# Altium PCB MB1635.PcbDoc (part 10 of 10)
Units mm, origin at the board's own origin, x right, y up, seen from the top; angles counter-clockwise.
Board outline 127 x 97 mm, 6 copper layers (Top Layer, Signal Layer 1, Signal Layer 2, Signal Layer 3, Signal Layer 4, Bottom Layer), stack 1.557 mm thick; 593 components, 478 nets, 2435 pads, 1743 vias.
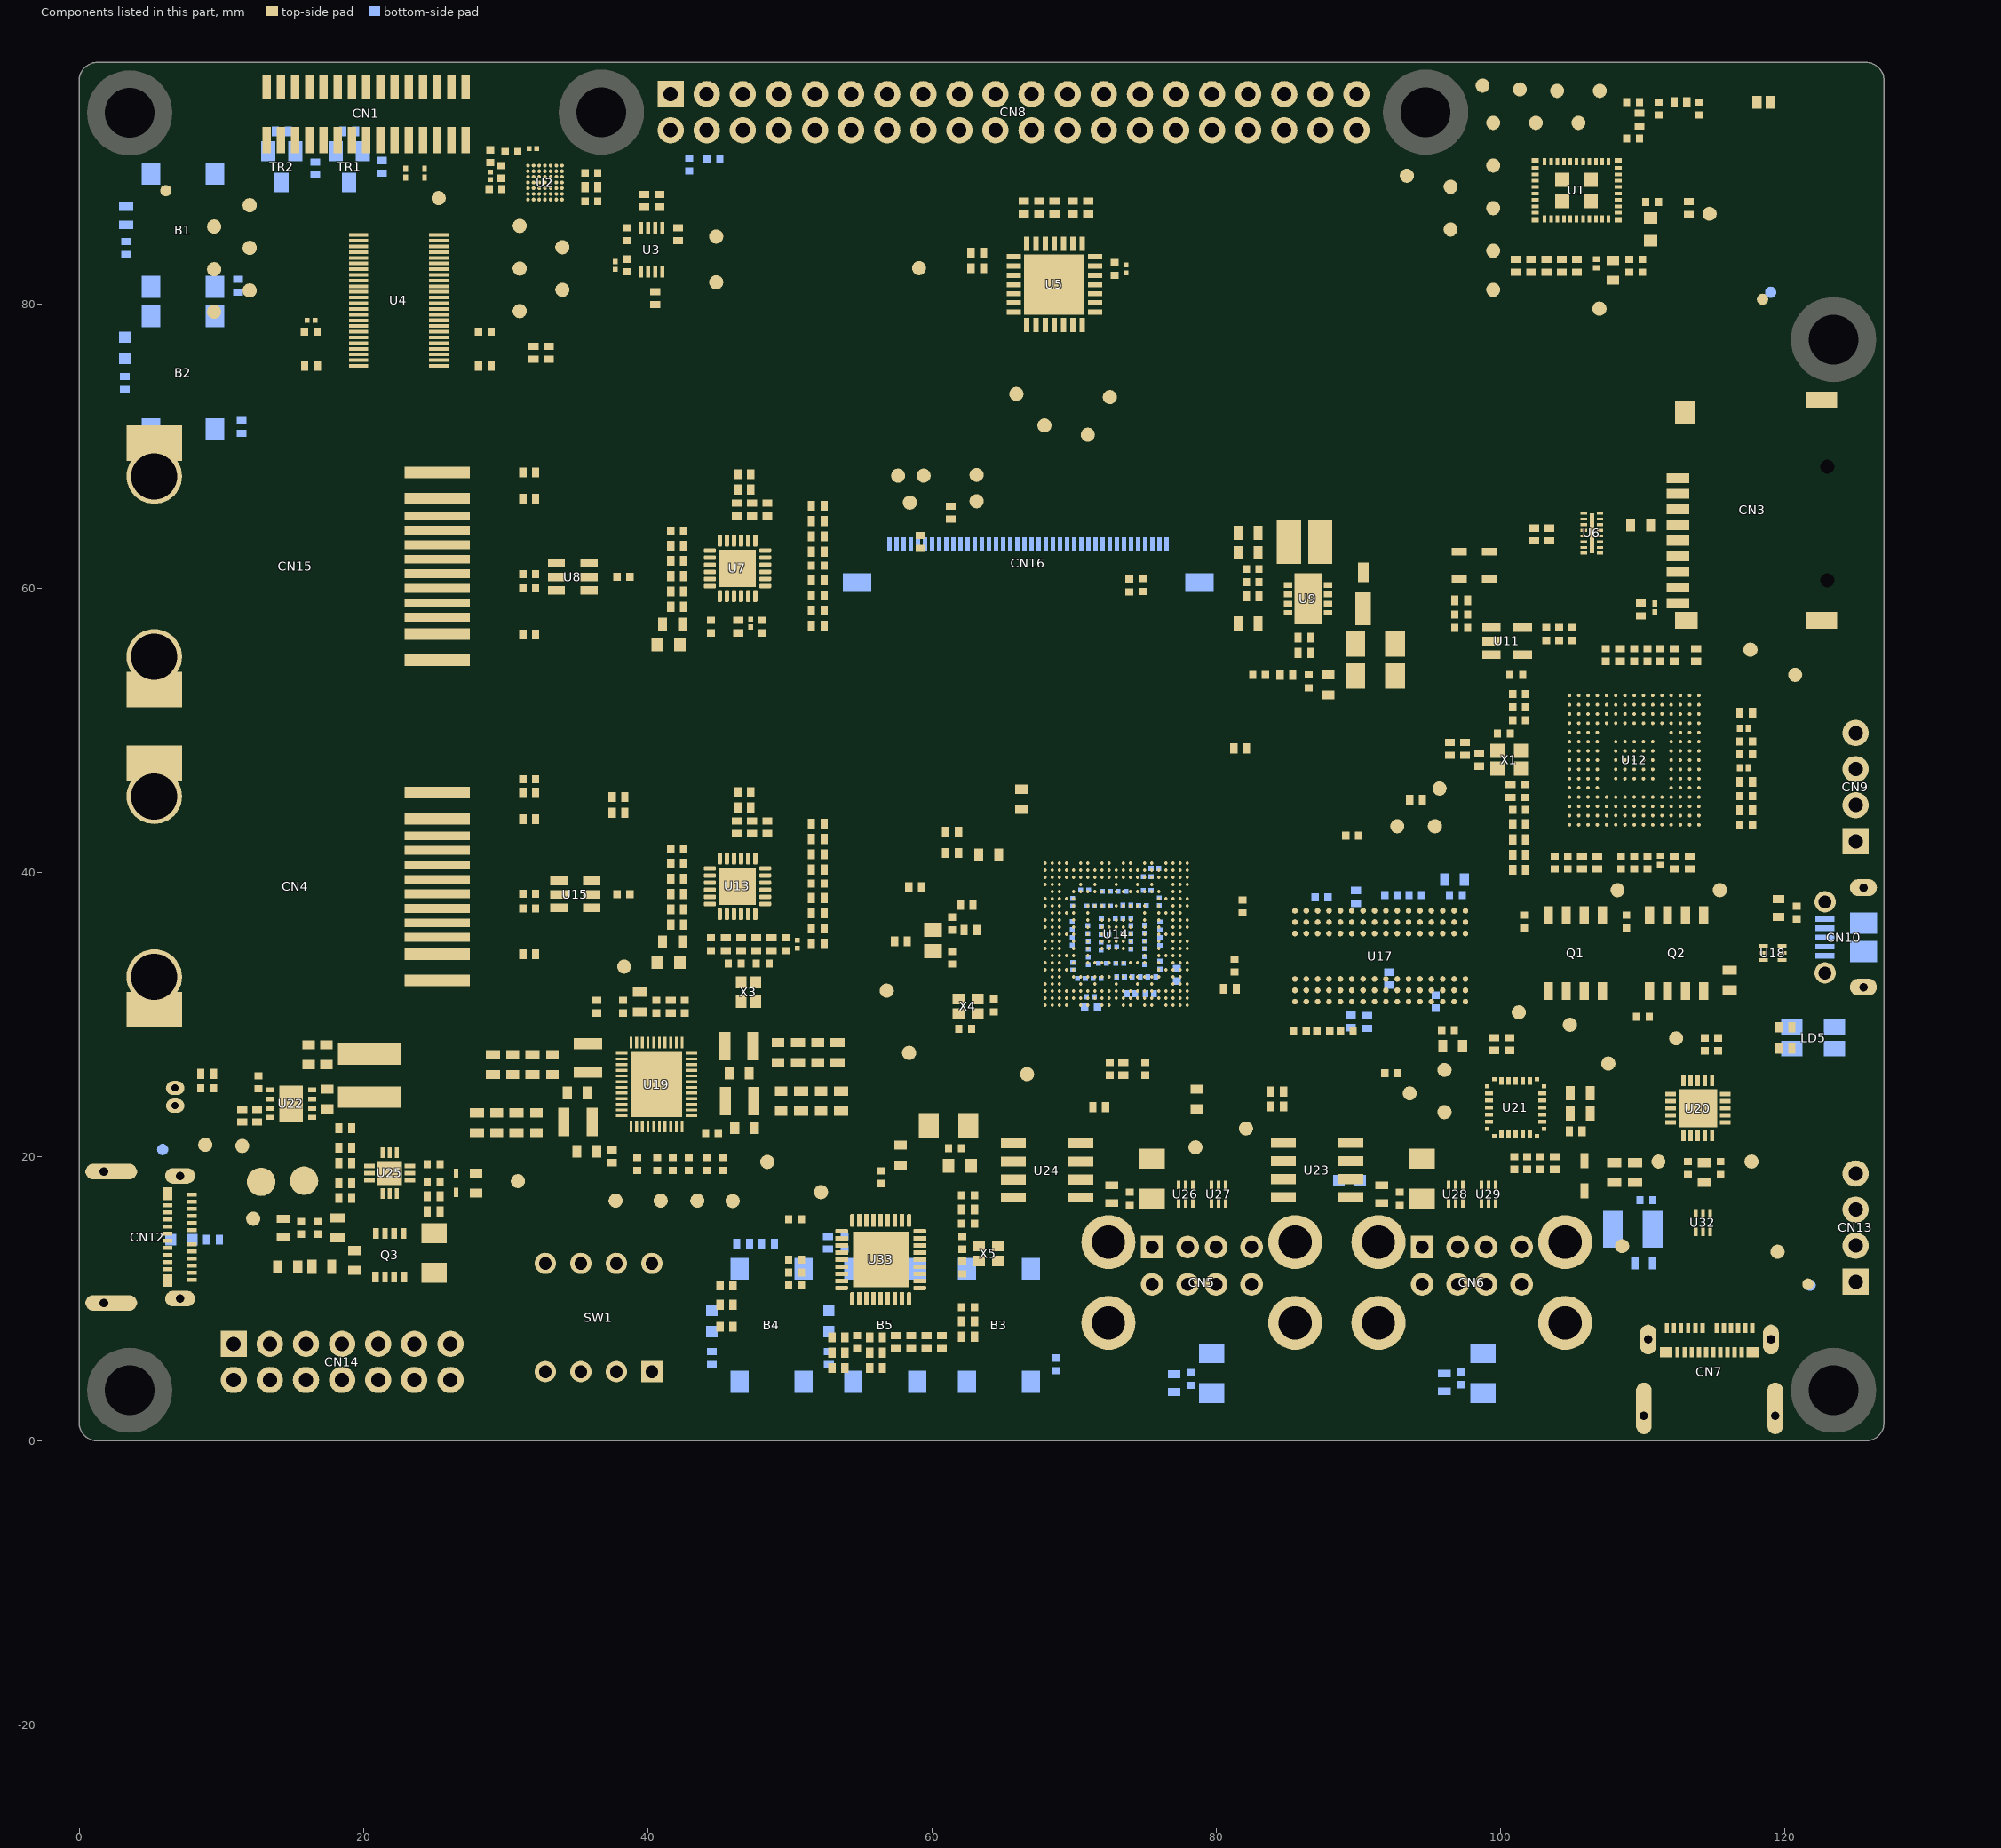
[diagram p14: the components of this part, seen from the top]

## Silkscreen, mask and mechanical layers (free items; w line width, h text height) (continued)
Bottom Overlay:
  lines w0.1: 44.75,48.05 55.325,48.05 57.375,50.1 65.3,50.1 65.3,28.225 43.8,28.225 43.8,48.05 44.8,48.05 ; 65.325,36.875 68.725,36.875 ; 68.375,36.525 68.725,36.875 ; 68.375,37.225 68.725,36.875
  lines w0.12: 5.175,30.95 1.995,30.95 1.995,47.05 5.175,47.05 ; 5.175,53.48 1.995,53.48 1.995,69.58 5.175,69.58 ; 9.375,30.95 13.25,30.95 ; 9.375,47.05 13.25,47.05 ; 9.375,69.58 13.35,69.58
  text "USER1" at 0.45,84.3 h1.5 r270
  text "USER2" at 0.45,74.1 h1.5 r270
  text "ETH2" at 11.175,61.25 h3
  text "RESERVED" at 121.15,42.225 h1.5 r270
  text "ETH1" at 10.875,37.95 h3
  text "USB_STLINK" at 120.8,31.75 h1.5 r270
  text "BOOT1" at 37.407,13.825 h1.5 r270
  text "BOOT2" at 34.857,13.8 h1.5 r270
  text "BOOT0" at 39.832,13.725 h1.5 r270
  text "NC" at 23.1,8.475 h1.5 r270
  text "VDD" at 25.65,8.475 h1.5 r270
  text "USB" at 15.575,8.4 h1.5 r270
  text "CPU" at 10.525,8.375 h1.3 r270
  text "GND" at 18.025,8.35 h1.5 r270
  text "CORE" at 20.55,8.35 h1.5 r270
  text "DDR" at 12.975,8.25 h1.5 r270
  text "WAKE_UP" at 67.9,2.275 h1.5
  text "TAMPER" at 51.475,2.225 h1.5
  text "RESET" at 59.2,2.225 h1.5
Top Solder:
  region: 114.325,24.8 114.325,23.825 115.3,23.825 115.3,24.8
  region: 115.3,22.975 114.325,22.975 114.325,22 115.3,22
  region: 113.475,22 113.475,22.975 112.5,22.975 112.5,22
  rectangle: 112.5,23.825 113.475,24.8
  region: 56.825,14.75 56.825,13.175 58.4,13.175 58.4,14.75
  region: 58.4,12.325 56.825,12.325 56.825,10.75 58.4,10.75
  region: 55.975,10.75 55.975,12.325 54.4,12.325 54.4,10.75
  rectangle: 54.4,13.175 55.975,14.75
  region: 15.8,25.05 15.275,25.05 15.275,24.075 15.8,24.075
  rectangle: 14.05,22.4 14.575,23.375
  region: 15.8,23.375 15.275,23.375 15.275,22.4 15.8,22.4
  rectangle: 14.05,24.075 14.575,25.05
  region: 47.675,38.6 46.75,38.6 46.75,37.675 47.675,37.675
  region: 45.9,37.675 45.9,38.6 44.975,38.6 44.975,37.675
  rectangle: 44.975,39.45 45.9,40.375
  region: 46.75,40.375 46.75,39.45 47.675,39.45 47.675,40.375
  region: 46.75,62.75 46.75,61.825 47.675,61.825 47.675,62.75
  region: 47.675,60.975 46.75,60.975 46.75,60.05 47.675,60.05
  region: 45.9,60.05 45.9,60.975 44.975,60.975 44.975,60.05
  rectangle: 44.975,61.825 45.9,62.75
  rectangle: 69.05,79.2 70.8,80.95
  rectangle: 66.45,79.2 68.2,80.95
  rectangle: 69.05,81.8 70.8,83.55
  rectangle: 66.45,81.8 68.2,83.55
  rectangle: 106.75,62.325 107.3,65.425
  rectangle: 105.6,62.325 106.15,65.425
  rectangle: 24.586,75.487 26.013,85.013
  rectangle: 18.936,75.487 20.363,85.013
  region: 121.8,17.425 123.55,17.425 123.55,25.05 121.8,25.05
Bottom Solder:
  region: 121.8,17.425 123.55,17.425 123.55,25.05 121.8,25.05
M1-Board Shape:
  the board outline again, w0.1
M7-Top Info:
  text "Raspberry shield standard max width is 65mm" at 53.5,103.038 h1.8
Drill Drawing:
  drawing of 528 lines, arcs and shapes, not listed
  text "MINIMUN PARAMETERS" at 152.3,145.65 h3
  text "PCB SPECIFICATIONS :" at 0.575,144.95 h3
  text "A.   MATERIAL :" at 0.575,140.95 h3
  text "FR-4" at 39.075,140.95 h3
  text "TG-170" at 55.575,140.95 h3
  text "X  TG-150" at 73.825,140.95 h3
  text "TG-140" at 89.825,140.95 h3
  text "DEFAULT" at 152.3,140.15 h3
  text "B.   MATERIAL FAMILY :" at 0.575,137.95 h3
  text "N/A" at 39.075,137.95 h3
  text "C.   SOLDERMASK COLOR :" at 0.575,134.95 h3
  text "GREEN" at 39.075,134.95 h3
  text "X  BLUE" at 55.575,134.95 h3
  text "RED" at 73.825,134.95 h3
  text "BLACK" at 89.825,134.95 h3
  text "TRACKS : 0.100mm           / GAPS : 0.100mm" at 152.3,134.4 h3
  text "D.   SILKSCREEN COLOR :" at 0.575,131.95 h3
  text "X  WHITE" at 39.075,131.95 h3
  text "YELLOW" at 55.575,131.95 h3
  text "BLACK" at 73.825,131.95 h3
  text "E.   SURFACE FINISH :" at 0.575,128.95 h3
  text "X  ENIG" at 39.075,128.95 h3
  text "IMMERSION SILVER" at 55.575,128.95 h3
  text "IMMERSION TIN" at 89.825,128.95 h3
  text "UNDER MPU" at 152.3,127.9 h3
  text "HASL" at 39.075,125.95 h3
  text "HASL (PB-FREE)" at 55.575,125.95 h3
  text "GOLDEN FINGER" at 89.825,125.95 h3
  text "F.   IMPEDANCE CONTROL :" at 0.575,122.95 h3
  text "NO" at 39.075,122.95 h3
  text "X  YES  (SEE IMPEDANCE TABLE FOR DETAIL INFORMATION)" at 55.575,122.95 h3
  text "TRACKS : 0.090mm           / GAPS : 0.080mm" at 152.3,122.15 h3
  text "G.   THROUGH VIA :" at 0.575,119.95 h3
  text "PLUG THE VIAS WHICH ARE COVERED WITH SOLDERMASK ONE OR TWO SIDE." at 39.075,119.95 h3
  text "PLUG MATERIAL :" at 39.075,116.95 h3
  text "X  SOLDERMASK" at 64.575,116.95 h3
  text "NON-CONDUCTIVE EPOXY." at 89.825,116.95 h3
  text "UNDER DDR" at 152.3,115.9 h3
  text "H.   STACK-UP :" at 0.575,113.95 h3
  text "SEE LAYER STACK-UP SEQUENCE FOR OVERALL THICKNESS." at 39.075,113.95 h3
  text "TRACKS : 0.090mm           / GAPS : 0.080mm" at 152.3,110.15 h3
  text "Layer" at 137.6,103.625 h2
  text "Name" at 145.974,103.625 h2
  text "Material" at 162.171,103.625 h2
  text "Thickness" at 176.725,103.625 h2
  text "Constant" at 188.68,103.625 h2
  text "Board Layer Stack" at 199.744,103.625 h2
  text "Top Overlay" at 145.974,99.625 h2
  text "Top Solder" at 145.974,95.625 h2
  text "Solder Resist" at 162.171,95.625 h2
  text "0.025mm" at 176.725,95.625 h2
  text "3.5" at 188.68,95.625 h2
  text "1" at 137.6,91.625 h2
  text "Top Layer" at 145.974,91.625 h2
  text "0.027mm" at 176.725,91.625 h2
  text "Dielectric 1" at 145.974,87.625 h2
  text "0.068mm" at 176.725,87.625 h2
  text "4" at 188.68,87.625 h2
  text "2" at 137.598,83.625 h2
  text "Signal Layer 1" at 145.974,83.625 h2
  text "0.033mm" at 176.725,83.625 h2
  text "Dielectric 2" at 145.974,79.625 h2
  text "0.510mm" at 176.725,79.625 h2
  text "4" at 188.68,79.625 h2
  text "3" at 137.6,75.625 h2
  text "Signal Layer 2" at 145.974,75.625 h2
  text "0.033mm" at 176.725,75.625 h2
  text "Dielectric 3" at 145.974,71.625 h2
  text "0.215mm" at 176.725,71.625 h2
  text "5" at 188.68,71.625 h2
  text "4" at 137.6,67.625 h2
  text "Signal Layer 3" at 145.974,67.625 h2
  text "0.033mm" at 176.725,67.625 h2
  text "Dielectric 4" at 145.974,63.625 h2
  text "0.510mm" at 176.725,63.625 h2
  text "4" at 188.68,63.625 h2
  text "5" at 137.6,59.625 h2
  text "Signal Layer 4" at 145.974,59.625 h2
  text "0.033mm" at 176.725,59.625 h2
  text "Dielectric5" at 145.974,55.625 h2
  text "0.068mm" at 176.725,55.625 h2
  text "4" at 188.68,55.625 h2
  text "6" at 137.6,51.625 h2
  text "Bottom Layer" at 145.974,51.625 h2
  text "0.027mm" at 176.725,51.625 h2
  text "Bottom Solder" at 145.974,47.625 h2
  text "Solder Resist" at 162.171,47.625 h2
  text "0.025mm" at 176.725,47.625 h2
  text "3.5" at 188.68,47.625 h2
  text "Bottom Overlay" at 145.974,43.625 h2
  text "Symbol" at 138.02,31.831 h2.4
  text "Count" at 147.419,31.831 h2.4
  text "Hole Size" at 158.05,31.831 h2.4
  text "Plated" at 177.321,31.831 h2.4
  text "Hole Type" at 185.572,31.831 h2.4
  text "Drill Layer Pair" at 197.584,31.831 h2.4
  text "Via/Pad" at 220.808,31.831 h2.4
  text "Pad Shape" at 230.651,31.831 h2.4
  text "Template" at 243.509,31.831 h2.4
  text "Hole Tolerance (+)" at 272.399,31.831 h2.4
  text "Hole Tolerance (-)" at 292.478,31.831 h2.4
  text "2" at 147.419,27.688 h2
  text "0.500mm (19.69mil)" at 158.05,27.688 h2
  text "PTH" at 177.321,27.688 h2
  text "Round" at 185.572,27.688 h2
  text "Top Layer - Bottom Layer" at 197.584,27.688 h2
  text "Pad" at 220.808,27.688 h2
  text "Rounded" at 230.651,27.688 h2
  text "(Mixed)" at 243.509,27.688 h2
  text "0.050mm (1.97mil)" at 272.399,27.688 h2
  text "0.050mm (1.97mil)" at 292.478,27.688 h2
  text "2" at 147.419,23.545 h2
  text "0.600mm (23.62mil)" at 158.05,23.545 h2
  text "PTH" at 177.321,23.545 h2
  text "Slot" at 185.572,23.545 h2
  text "Top Layer - Bottom Layer" at 197.584,23.545 h2
  text "Pad" at 220.808,23.545 h2
  text "Rounded" at 230.651,23.545 h2
  text "r190_120h60_130r100m195_125" at 243.509,23.545 h2
  text "2" at 147.419,19.402 h2
  text "1.000mm (39.37mil)" at 158.05,19.402 h2
  text "NPTH" at 177.321,19.402 h2
  text "Round" at 185.572,19.402 h2
  text "Top Layer - Bottom Layer" at 197.584,19.402 h2
  text "Pad" at 220.808,19.402 h2
  text "Rounded" at 230.651,19.402 h2
  text "c50hn100m105p-1" at 243.509,19.402 h2
  text "4" at 147.419,15.259 h2
  text "0.600mm (23.62mil)" at 158.05,15.259 h2
  text "PTH" at 177.321,15.259 h2
  text "Slot" at 185.572,15.259 h2
  text "Top Layer - Bottom Layer" at 197.584,15.259 h2
  text "Pad" at 220.808,15.259 h2
  text "Rounded" at 230.651,15.259 h2
  text "r210_110h60_160r100m215_115" at 243.509,15.259 h2
  text "4" at 147.419,11.115 h2
  text "0.600mm (23.62mil)" at 158.05,11.115 h2
  text "PTH" at 177.321,11.115 h2
  text "Slot" at 185.572,11.115 h2
  text "Top Layer - Bottom Layer" at 197.584,11.115 h2
  text "Pad" at 220.808,11.115 h2
  text "Rounded" at 230.651,11.115 h2
  text "r260_110h60_210r100m265_115" at 243.509,11.115 h2
  text "4" at 147.419,6.972 h2
  text "3.250mm (127.95mil)" at 158.05,6.972 h2
  text "PTH" at 177.321,6.972 h2
  text "Round" at 185.572,6.972 h2
  text "Top Layer - Bottom Layer" at 197.584,6.972 h2
  text "Pad" at 220.808,6.972 h2
  text "Rounded" at 230.651,6.972 h2
  text "c390h325m395" at 243.509,6.972 h2
  text "6" at 147.419,2.829 h2
  text "3.500mm (137.79mil)" at 158.05,2.829 h2
  text "PTH" at 177.321,2.829 h2
  text "Round" at 185.572,2.829 h2
  text "Top Layer - Bottom Layer" at 197.584,2.829 h2
  text "Pad" at 220.808,2.829 h2
  text "Rounded" at 230.651,2.829 h2
  text "c600h350" at 243.509,2.829 h2
  text "8" at 147.419,-1.314 h2
  text "2.330mm (91.73mil)" at 158.05,-1.314 h2
  text "PTH" at 177.321,-1.314 h2
  text "Round" at 185.572,-1.314 h2
  text "Top Layer - Bottom Layer" at 197.584,-1.314 h2
  text "Pad" at 220.808,-1.314 h2
  text "Rounded" at 230.651,-1.314 h2
  text "c380h233" at 243.509,-1.314 h2
  text "10" at 147.419,-5.457 h2
  text "0.900mm (35.43mil)" at 158.05,-5.457 h2
  text "PTH" at 177.321,-5.457 h2
  text "Round" at 185.572,-5.457 h2
  text "Top Layer - Bottom Layer" at 197.584,-5.457 h2
  text "Pad" at 220.808,-5.457 h2
  text "(Mixed)" at 230.651,-5.457 h2
  text "(Mixed)" at 243.509,-5.457 h2
  text "16" at 147.419,-9.6 h2
  text "0.920mm (36.22mil)" at 158.05,-9.6 h2
  text "PTH" at 177.321,-9.6 h2
  text "Round" at 185.572,-9.6 h2
  text "Top Layer - Bottom Layer" at 197.584,-9.6 h2
  text "Pad" at 220.808,-9.6 h2
  text "(Mixed)" at 230.651,-9.6 h2
  text "(Mixed)" at 243.509,-9.6 h2
  text "29" at 147.419,-13.743 h2
  text "0.100mm (3.94mil)" at 158.05,-13.743 h2
  text "PTH" at 177.321,-13.743 h2
  text "Round" at 185.572,-13.743 h2
  text "Top Layer - Signal Layer 1" at 197.584,-13.743 h2
  text "Via" at 220.808,-13.743 h2
  text "Rounded" at 230.651,-13.743 h2
  text "v26h10m0" at 243.509,-13.743 h2
  text "62" at 147.419,-17.886 h2
  text "1.000mm (39.37mil)" at 158.05,-17.886 h2
  text "PTH" at 177.321,-17.886 h2
  text "Round" at 185.572,-17.886 h2
  text "Top Layer - Bottom Layer" at 197.584,-17.886 h2
  text "Pad" at 220.808,-17.886 h2
  text "Rounded" at 230.651,-17.886 h2
  text "(Mixed)" at 243.509,-17.886 h2
  text "276" at 147.419,-22.029 h2
  text "0.200mm (7.87mil)" at 158.05,-22.029 h2
  text "PTH" at 177.321,-22.029 h2
  text "Round" at 185.572,-22.029 h2
  text "Top Layer - Bottom Layer" at 197.584,-22.029 h2
  text "Via" at 220.808,-22.029 h2
  text "Rounded" at 230.651,-22.029 h2
  text "v40h20m20" at 243.509,-22.029 h2
  text "1438" at 147.419,-26.172 h2
  text "0.250mm (9.84mil)" at 158.05,-26.172 h2
  text "PTH" at 177.321,-26.172 h2
  text "Round" at 185.572,-26.172 h2
  text "Top Layer - Bottom Layer" at 197.584,-26.172 h2
  text "Via" at 220.808,-26.172 h2
  text "Rounded" at 230.651,-26.172 h2
  text "(Mixed)" at 243.509,-26.172 h2
  text "1863 Total" at 147.419,-30.315 h2
  text "Slot definitions :" at 138.02,-33.216 h2
  text "Routed Path Length" at 151.673,-33.216 h2
  text "= Calculated from tool start centre position to tool end centre position." at 168.586,-33.216 h2
  text "Hole Length" at 151.673,-34.873 h2
  text "= Routed Path Length + Tool Size = Slot length as defined in the PCB layout" at 162.307,-34.873 h2

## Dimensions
127,95.73 to 0,95.73 on M2-Board Dimensions
33.15,96.75 to 98.15,97.025 on M8-Bottom Info
1.27,0 to 1.27,97 on M2-Board Dimensions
